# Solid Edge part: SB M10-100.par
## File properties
Title: Shoulder Bolt
Author: Dan
Template: Shoulder Bolt.par
Last saved by: Dan
Revision: 6
Application: Solid Edge
Material: Steel
Face Style: Steel
Fill Style: ANSI32(Steel)
Virtual Style: Machined steel
Coef. of Thermal Exp: 1.3e-05
Thermal Conductivity: 32.0
Specific Heat: 481.0
Modulus of Elasticity: 199947953000.0
Poisson's Ratio: 0.29
Yield Stress: 262000766.0
Ultimate Stress: 358527364.0
Elongation: 0.0
Density: 0.000007833 kg/mm^3
Accuracy: 0.99
Document Number: SBM -
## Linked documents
Shoulder Bolt.par
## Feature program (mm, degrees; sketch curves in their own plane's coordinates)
part copy "CopiedPart_1"
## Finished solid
Body 1: solid body, 16 faces, 26 edges, 12 vertices.
  Faces by surface: plane 11, cylinder 3, cone 1, torus 1
  Edges by curve: line 18, circle 8
Bounding box of the edges (mm; curved faces can reach further): 121.000 x 18.000 x 18.000, from (-109, -9, -9) to (12, 9, 9).
Cylindrical faces by radius (mm): R5 x1, R6 x1, R9 x1
Conical faces (half-angle, radius in mm at the cone's reference point): 45 deg R5 x1
Toroidal faces (ring radius, tube radius in mm): R8 r1 x1
Planar faces by outward normal: +x 3, +z 1, -x 2, -z 1, oblique 4
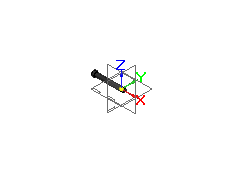
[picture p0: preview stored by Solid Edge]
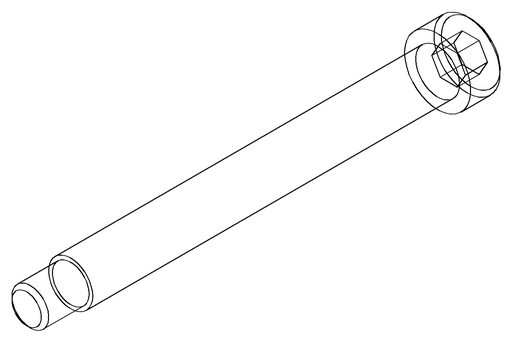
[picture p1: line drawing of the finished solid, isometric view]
